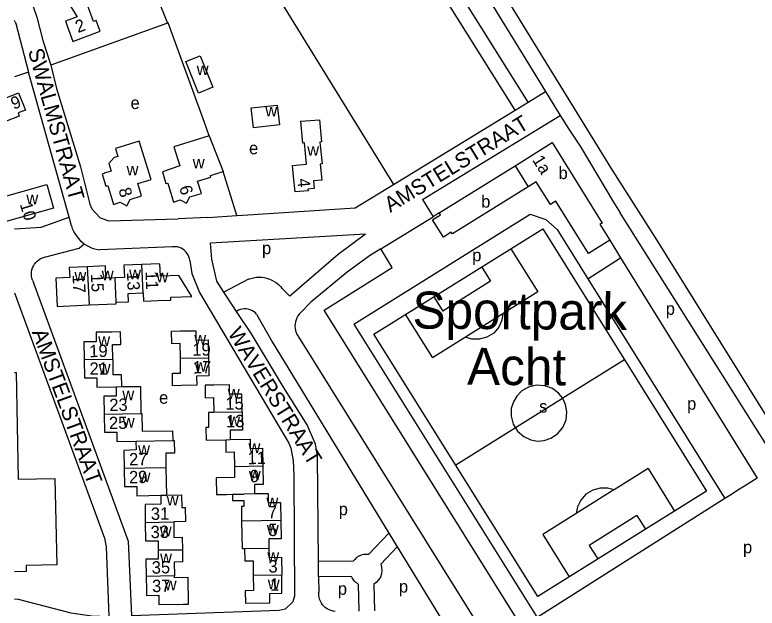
# Model space of a CAD drawing. Extents: x 156721 to 158827, y 386657 to 388950.
# Drawn here: x 158050.1 to 158290.7, y 387994 to 388186.3 of the extents above; entities that cross this region are included whole.
import ezdxf

# ---------------------------------------------------------------- set-up
doc = ezdxf.new("R2010")
doc.units = 0
for name, color, linetype in [('BLT_Basislijn', 7, 'Continuous'), ('BLT_Bebouwing', 7, 'Continuous'), ('BLT_Centroide', 7, 'Continuous'), ('BLT_Huisnummer', 7, 'Continuous'), ('BLT_Huisnummer_ tussenligend', 7, 'Continuous'), ('BLT_Onderverdeling_panden', 7, 'Continuous'), ('BLT_Sport_parknaam', 7, 'Continuous'), ('BLT_Straatnaam', 7, 'Continuous')]:
    doc.layers.add(name, color=color, linetype=linetype)

msp = doc.modelspace()

# ---------------------------------------------------------------- linework, layer by layer
at = {"layer": 'BLT_Basislijn'}
for p, q in [((158216.53, 388157.97), (158147.78, 388267.77)), ((158212.27, 388155.37), (158143.53, 388265.14)), ((158105, 388241.26), (158172.89, 388131.34)), ((158087.82, 388213.04), (158099.56, 388183.62)), ((158050.2, 388183.97), (158050, 388184.5)), ((158099.76, 388183.7), (158099.56, 388183.62)), ((158111.56, 388151.36), (158099.76, 388183.7)), ((158099.56, 388183.62), (158061.73, 388169.97)), ((158054.58, 388167.7), (158050, 388166.22)), ((158067.66, 388120.71), (158054.58, 388167.7)), ((158216.53, 388157.97), (158222.16, 388161.41)), ((158222.16, 388161.41), (158226.92, 388153.69)), ((158212.27, 388155.37), (158216.53, 388157.97)), ((158172.89, 388131.34), (158212.27, 388155.37)), ((158182.27, 388126.44), (158226.92, 388153.69)), ((158113.09, 388147.11), (158111.56, 388151.36)), ((158122.11, 388121.26), (158117.59, 388135.49)), ((158160.45, 388123.74), (158172.89, 388131.34)), ((158182.27, 388126.44), (158185.68, 388120.85)), ((158112.68, 388120.58), (158122.11, 388121.26)), ((158160.03, 388086), (158217.12, 388121.66)), ((158187.7, 388122.09), (158185.68, 388120.85)), ((158217.12, 388121.66), (158222.21, 388119.95)), ((158297.68, 388040.58), (158246.38, 388122.14)), ((158058.68, 388117.43), (158067.66, 388120.71)), ((158068.43, 388117.96), (158067.66, 388120.71)), ((158112.68, 388120.58), (158103.1, 388120.13)), ((158168.71, 388110.47), (158185.68, 388120.85)), ((158222.21, 388119.95), (158225.87, 388116.67)), ((158050, 388116.95), (158058.68, 388117.43)), ((158225.87, 388116.67), (158235.81, 388100.75)), ((158163.81, 388115.18), (158113.51, 388112.31)), ((158163.81, 388115.18), (158154.91, 388108.58)), ((158242.94, 388113.3), (158246.4, 388107.49)), ((158101.21, 388111.11), (158077.65, 388110.14)), ((158168.71, 388110.47), (158165.02, 388108.21)), ((158172.47, 388104.45), (158168.71, 388110.47)), ((158210.87, 388110.44), (158219.59, 388096.47)), ((158154.91, 388108.58), (158139.24, 388095.09)), ((158235.81, 388100.75), (158246.4, 388107.49)), ((158246.4, 388107.49), (158290.74, 388036.17)), ((158150.33, 388090.62), (158172.47, 388104.45)), ((158201.46, 388104.56), (158204.35, 388099.93)), ((158125.82, 388100.6), (158117.9, 388096.39)), ((158204.35, 388099.93), (158188.87, 388090.27)), ((158235.81, 388100.75), (158280.3, 388029.55)), ((158136.93, 388097.4), (158139.24, 388095.09)), ((158120.94, 388091.61), (158117.9, 388096.39)), ((158185.98, 388094.89), (158188.87, 388090.27)), ((158219.59, 388096.47), (158208.4, 388089.48)), ((158121.91, 388090.17), (158120.94, 388091.61)), ((158126.82, 388082.87), (158121.91, 388090.17)), ((158214.51, 387987.88), (158150.33, 388090.62)), ((158128.4, 388089.32), (158133.48, 388080.33)), ((158176.72, 388089.1), (158185.45, 388075.14)), ((158208.31, 388089.42), (158185.45, 388075.14)), ((158160.03, 388086), (158219.41, 387990.94)), ((158133.48, 388080.33), (158171.34, 388018.28)), ((158142.05, 388081.92), (158199.09, 387990.42)), ((158247.73, 388074.5), (158227.74, 388062.01)), ((158227.68, 388061.98), (158193.06, 388040.35)), ((158255.36, 388039.23), (158244.42, 388032.39)), ((158255.36, 388039.23), (158263.94, 388025.49)), ((158290.74, 388036.17), (158286.63, 388033.57)), ((158244.33, 388032.34), (158221.21, 388017.89)), ((158284.52, 388032.23), (158282.41, 388030.89)), ((158286.63, 388033.57), (158284.52, 388032.23)), ((158282.41, 388030.89), (158280.3, 388029.55)), ((158280.3, 388029.55), (158219.41, 387990.94)), ((158251.76, 388024.04), (158236.29, 388014.37)), ((158251.76, 388024.04), (158254.53, 388019.61)), ((158171.34, 388018.28), (158164.77, 388011.36)), ((158171.34, 388018.28), (158174.04, 388013.86)), ((158221.21, 388017.89), (158229.79, 388004.16)), ((158174.04, 388013.86), (158168.72, 388008.26)), ((158174.04, 388013.86), (158192.54, 387983.8)), ((158236.29, 388014.37), (158239.05, 388009.95)), ((158159.77, 388009.22), (158148.53, 388009.14)), ((158148.57, 388004.14), (158148.53, 388009.14)), ((158159.29, 388004.22), (158148.57, 388004.14)), ((158148.57, 388004.14), (158148.61, 387999.21)), ((158161.45, 388001.83), (158161.64, 387993.07)), ((158166.45, 388001.8), (158166.64, 387993.15))]:
    msp.add_line(p, q, dxfattribs=at)
for points in [[(158087.6, 388388.98), (158120.58, 388335.72), (158121.32, 388334.13), (158168.5, 388258.11), (158180.9, 388237.55), (158193.49, 388217.63), (158243.23, 388136.8), (158258.3, 388113.07), (158338.44, 387984.38), (158433.27, 387830.65)], [(158157.81, 388264.96), (158189.98, 388213.68), (158222.16, 388161.41)], [(158054.85, 388192.54), (158057.24, 388185.58), (158059.18, 388178.02), (158061.73, 388169.97)], [(158050.2, 388183.97), (158050.41, 388183.44), (158054.58, 388167.7)], [(158061.73, 388169.97), (158063.64, 388162.44), (158071.36, 388137.04), (158074.42, 388124.88), (158075.04, 388123.39), (158077.78, 388120.52), (158080.62, 388119.56), (158103.1, 388120.13)], [(158226.92, 388153.69), (158229.68, 388149.2), (158233.35, 388143.7), (158244.21, 388125.6), (158246.38, 388122.14)], [(158122.11, 388121.26), (158124.02, 388121.4), (158160.45, 388123.74)], [(158068.43, 388117.96), (158068.72, 388117.08), (158069.09, 388116.22), (158069.53, 388115.4), (158070.05, 388114.62), (158070.62, 388113.88), (158071.26, 388113.2), (158071.95, 388112.57), (158072.56, 388112.11)], [(158060.15, 388107.89), (158071, 388110.63), (158072.56, 388112.11)], [(158072.56, 388112.11), (158072.69, 388112.01), (158073.48, 388111.51), (158074.31, 388111.08), (158075.18, 388110.72), (158076.07, 388110.44), (158076.98, 388110.24), (158077.65, 388110.14)], [(158117.9, 388096.39), (158115.61, 388099.99), (158114, 388107.09), (158113.51, 388112.31)], [(158106.79, 388106.65), (158106.69, 388107.27), (158106.52, 388107.88), (158106.27, 388108.45), (158105.95, 388108.99), (158105.56, 388109.49), (158105.11, 388109.93), (158104.61, 388110.32), (158104.07, 388110.63), (158103.49, 388110.88), (158102.88, 388111.05), (158102.26, 388111.14), (158101.63, 388111.15), (158101.21, 388111.11)], [(158055.84, 388100.29), (158055.64, 388100.93), (158055.52, 388101.6), (158055.48, 388102.27), (158055.52, 388102.95), (158055.64, 388103.61), (158055.84, 388104.26), (158056.11, 388104.88), (158056.46, 388105.46), (158056.87, 388106), (158057.34, 388106.48), (158057.86, 388106.91), (158058.43, 388107.27), (158059.04, 388107.56), (158059.68, 388107.78), (158060.15, 388107.89)], [(158165.02, 388108.21), (158157.8, 388102.89), (158146.07, 388093.13), (158142.74, 388089.76)], [(158106.79, 388106.65), (158107.45, 388102.46), (158110.01, 388096.33), (158138.9, 388047.47), (158139.54, 388045.87), (158140.34, 388041.81), (158140.5, 388037.02), (158140.79, 387997.94), (158140.18, 387996.05), (158137.77, 387993.71), (158135.81, 387993.26), (158087.96, 387991.51)], [(158055.84, 388100.29), (158086.82, 388015.72), (158087.96, 387991.51)], [(158125.82, 388100.6), (158126.64, 388100.88), (158127.48, 388101.09), (158128.34, 388101.22), (158129.21, 388101.27), (158130.08, 388101.24), (158130.94, 388101.13), (158131.79, 388100.94), (158132.62, 388100.67), (158133.42, 388100.33), (158134.18, 388099.92), (158134.9, 388099.44), (158135.58, 388098.89), (158136.2, 388098.28), (158136.77, 388097.62), (158136.93, 388097.4)], [(158050, 388096.15), (158079.12, 388016.74), (158079.71, 388013.9), (158080.59, 387991.28)], [(158128.4, 388089.32), (158127.96, 388089.77), (158127.46, 388090.15), (158126.91, 388090.47), (158126.33, 388090.72), (158125.73, 388090.89), (158125.1, 388090.99), (158124.47, 388091), (158123.84, 388090.93), (158123.23, 388090.79), (158122.64, 388090.57), (158122.08, 388090.28), (158121.91, 388090.17)], [(158142.74, 388089.76), (158142.27, 388089.25), (158141.86, 388088.69), (158141.52, 388088.09), (158141.25, 388087.45), (158141.06, 388086.79), (158140.94, 388086.1), (158140.9, 388085.41), (158140.95, 388084.72), (158141.07, 388084.04), (158141.27, 388083.37), (158141.55, 388082.74), (158141.9, 388082.14), (158142.05, 388081.92)], [(158208.34, 388089.44), (158208, 388087.29), (158207.02, 388085.11), (158205.35, 388083.16), (158203.13, 388081.78), (158200.65, 388081.13), (158198.25, 388081.2), (158196.18, 388081.84)], [(158148.53, 388009.14), (158148.24, 388043.32), (158147.53, 388047.15), (158144.91, 388053.47), (158137.23, 388065.6), (158126.82, 388082.87)], [(158227.7, 388062.01), (158226.34, 388063.7), (158224.4, 388065.15), (158221.96, 388066.08), (158219.26, 388066.27), (158216.64, 388065.66), (158214.43, 388064.39), (158212.78, 388062.73), (158211.7, 388060.91), (158211.05, 388058.74), (158210.98, 388056.25), (158211.65, 388053.68), (158213.07, 388051.37), (158215.06, 388049.62), (158217.32, 388048.57), (158219.55, 388048.18), (158221.66, 388048.32), (158223.88, 388049.05), (158226.01, 388050.46), (158227.73, 388052.52), (158228.78, 388055.02), (158229.05, 388057.61), (158228.62, 388060), (158227.72, 388061.97)], [(158244.37, 388032.36), (158242.27, 388032.93), (158239.88, 388032.95), (158237.44, 388032.27), (158235.24, 388030.9), (158233.56, 388029), (158232.53, 388026.85), (158232.12, 388024.71)], [(158164.77, 388011.36), (158163.98, 388011.42), (158163.17, 388011.36), (158162.35, 388011.16), (158161.58, 388010.83), (158160.88, 388010.38), (158160.27, 388009.83), (158159.77, 388009.22)], [(158168.72, 388008.26), (158169.01, 388007.29), (158169.11, 388006.23), (158168.97, 388005.13), (158168.6, 388004.08), (158168.02, 388003.14), (158167.28, 388002.37), (158166.45, 388001.8)], [(158161.45, 388001.83), (158161.06, 388002.08), (158160.69, 388002.36), (158160.34, 388002.68), (158160.02, 388003.03), (158159.74, 388003.4), (158159.5, 388003.8), (158159.29, 388004.22)], [(158153.97, 387992.94), (158153.3, 387993.03), (158152.63, 387993.21), (158152, 387993.45), (158151.39, 387993.77), (158150.83, 387994.16), (158150.32, 387994.62), (158149.87, 387995.12), (158149.47, 387995.68), (158149.15, 387996.28), (158148.89, 387996.92), (158148.72, 387997.58), (158148.62, 387998.25), (158148.6, 387998.94), (158148.61, 387999.21)], [(158050, 387997.06), (158051.18, 387996.93), (158068.22, 387992.53), (158075.01, 387991.54), (158080.59, 387991.28)]]:
    msp.add_lwpolyline(points, dxfattribs=at)
for points in [[(158105.53, 388171.11), (158110.13, 388172.98), (158114.28, 388162.81), (158109.67, 388160.93)], [(158219.62, 387997.74), (158166.49, 388082.77), (158221.25, 388116.98), (158274.37, 388031.95)]]:
    msp.add_lwpolyline(points, close=True, dxfattribs=at)
at = {"layer": 'BLT_Bebouwing'}
for p, q in [((158113.09, 388147.11), (158117.59, 388135.49)), ((158099.09, 388039.52), (158099.23, 388030.61))]:
    msp.add_line(p, q, dxfattribs=at)
for points in [[(158079.25, 388201.85), (158065.52, 388193.28), (158070.3, 388185.69), (158066.47, 388184.26), (158068.94, 388177.67), (158077.79, 388180.97), (158076.49, 388184.46), (158075.6, 388184.12), (158073.59, 388189.77), (158083.1, 388195.68)], [(158044.71, 388162.69), (158046.2, 388158.97), (158051.31, 388161.01), (158053.51, 388155.44), (158051.13, 388154.52), (158051.55, 388153.5), (158047.11, 388151.74), (158046.7, 388152.76), (158042.39, 388151.04), (158040.41, 388155.99), (158038.55, 388155.25), (158036.82, 388159.57)], [(158044.37, 388126.76), (158060.46, 388131.33), (158062.67, 388123.65), (158046.55, 388119.07)]]:
    msp.add_lwpolyline(points, close=True, dxfattribs=at)
for points in [[(158126.71, 388156.1), (158135.15, 388157.06), (158135.89, 388150.6), (158127.45, 388149.64), (158126.71, 388156.1)], [(158143.99, 388144.76), (158143.47, 388144.71), (158142.77, 388151.81), (158148.81, 388152.21), (158149.52, 388145.1), (158148.99, 388145.05)], [(158089.92, 388131.62), (158094.24, 388132.95), (158090.42, 388145.3), (158082.77, 388142.93), (158083.5, 388140.41), (158082.31, 388140.07), (158080.61, 388138.07), (158081.33, 388135.59), (158079.02, 388134.93), (158079.06, 388134.82), (158078.41, 388134.62), (158079.59, 388130.79), (158080.2, 388130.98), (158082.09, 388124.86), (158084.29, 388125.54), (158086.36, 388124.44), (158087.44, 388126.49), (158091.15, 388127.64), (158089.92, 388131.62)], [(158113.09, 388147.11), (158101.65, 388143.55), (158103.59, 388137.3), (158097.93, 388135.45), (158099.1, 388131.61), (158099.65, 388131.78), (158101.5, 388125.63), (158103.7, 388126.32), (158105.77, 388125.22), (158106.88, 388127.26), (158110.59, 388128.41), (158109.36, 388132.41), (158113.62, 388133.73), (158113.48, 388134.21), (158117.59, 388135.49)], [(158148.99, 388145.05), (158149.7, 388137.98), (158149.07, 388137.92), (158149.59, 388132.76), (158146.9, 388132.49), (158147.15, 388129.98), (158145.1, 388129.77), (158145.14, 388129.3), (158140.93, 388128.88), (158140.43, 388133.85), (158140.07, 388137.46), (158144.67, 388137.92), (158143.99, 388144.76)], [(158212.26, 388137.37), (158224.3, 388144.86), (158240.45, 388118.82), (158239.77, 388118.4), (158242.94, 388113.3)], [(158187.7, 388122.09), (158212.26, 388137.37)], [(158242.94, 388113.3), (158236.05, 388108.94), (158225.5, 388125.94), (158223.71, 388124.84), (158219.14, 388132.19), (158216.54, 388130.58)], [(158216.54, 388130.58), (158191.93, 388115.31), (158191.58, 388115.87), (158189.02, 388114.27), (158185.53, 388119.86), (158188.09, 388121.46), (158187.7, 388122.09)], [(158073.6, 388104.67), (158067.73, 388104.43), (158067.88, 388101.2), (158063.44, 388101), (158063.86, 388091.81), (158074.15, 388092.27)], [(158082.63, 388101.02), (158079.61, 388100.9), (158079.46, 388104.91), (158073.6, 388104.67)], [(158091.3, 388105.38), (158085.45, 388105.14), (158085.61, 388101.13), (158082.63, 388101.02)], [(158091.67, 388096.21), (158091.77, 388093.51), (158096.59, 388093.7), (158100.66, 388093.86), (158100.62, 388094.76), (158107.52, 388095.03), (158103.25, 388101.86), (158097.31, 388101.63), (158097.15, 388105.61), (158091.3, 388105.38)], [(158082.93, 388093.17), (158086.95, 388093.32), (158086.85, 388096.02), (158091.67, 388096.21)], [(158074.15, 388092.27), (158082.95, 388092.67), (158082.93, 388093.17)], [(158081.83, 388074.58), (158081.75, 388079.42), (158084.42, 388079.46), (158084.36, 388083.54), (158081.43, 388083.5), (158076.43, 388083.42), (158076.48, 388080.36), (158072.48, 388080.3), (158072.58, 388074.44)], [(158103.75, 388074.98), (158103.66, 388079.77), (158100.98, 388079.72), (158100.9, 388083.77), (158103.77, 388083.83), (158108.77, 388083.92), (158108.82, 388080.87), (158112.82, 388080.93), (158112.91, 388075.15)], [(158072.58, 388074.44), (158072.68, 388068.6), (158076.67, 388068.67), (158076.72, 388065.63), (158082.93, 388065.73)], [(158081.83, 388074.58), (158081.9, 388069.74), (158084.59, 388069.78), (158084.65, 388065.8)], [(158112.91, 388075.15), (158113.01, 388069.26), (158109.04, 388069.18), (158109.09, 388066.24), (158104.09, 388066.14), (158101.25, 388066.09), (158101.18, 388070.14), (158103.84, 388070.19), (158103.75, 388074.98)], [(158050, 388070.38), (158050.49, 388070.39), (158051.23, 388035.79), (158063.11, 388036.04), (158063.7, 388008.04), (158053.72, 388007.83), (158053.76, 388005.84), (158050, 388005.76)], [(158084.65, 388065.8), (158090.85, 388065.89), (158090.98, 388057.04)], [(158123.8, 388057.57), (158123.71, 388063.41), (158119.71, 388063.35), (158119.66, 388066.4), (158114.66, 388066.32), (158111.78, 388066.28), (158111.85, 388062.2), (158114.52, 388062.24), (158114.6, 388057.42)], [(158082.93, 388065.73), (158082.98, 388062.76), (158078.96, 388062.7), (158079.06, 388056.85)], [(158079.06, 388056.85), (158079.16, 388051), (158083.16, 388051.04), (158083.18, 388048), (158089.31, 388048.18)], [(158090.98, 388057.04), (158091.31, 388057.05), (158091.39, 388051.38), (158101.26, 388051.52), (158101.3, 388048.29)], [(158114.6, 388057.42), (158112.84, 388057.39), (158112.92, 388052.57), (158112, 388052.56), (158112.07, 388048.48), (158118.47, 388048.58)], [(158123.8, 388057.57), (158123.89, 388051.72), (158119.89, 388051.65), (158119.95, 388048.69)], [(158089.31, 388048.18), (158089.4, 388045.27), (158085.43, 388045.15), (158085.53, 388039.29)], [(158101.3, 388048.29), (158101.75, 388048.29), (158101.82, 388044.25), (158099.01, 388044.21), (158099.09, 388039.52)], [(158118.47, 388048.58), (158118.54, 388044.61), (158121.21, 388044.65), (158121.29, 388039.82)], [(158119.95, 388048.69), (158126.37, 388048.81), (158126.42, 388045.77), (158130.41, 388045.83), (158130.51, 388039.98)], [(158085.53, 388039.29), (158085.63, 388033.42), (158089.61, 388033.48), (158089.66, 388030.43), (158097.41, 388030.6)], [(158121.29, 388039.82), (158121.34, 388036.33), (158115.33, 388036.23), (158115.42, 388030.82), (158118.75, 388030.88), (158120.62, 388030.91)], [(158130.51, 388039.98), (158130.61, 388034.12), (158127.76, 388034.08), (158127.8, 388031.15)], [(158097.41, 388030.6), (158097.47, 388027.67), (158092.31, 388027.55), (158092.4, 388021.69)], [(158099.23, 388030.61), (158104.13, 388030.69), (158104.19, 388026.62), (158105.32, 388026.64), (158105.39, 388022.07), (158101.59, 388022.01), (158101.59, 388021.84)], [(158120.62, 388030.91), (158120.65, 388028.89), (158124.33, 388028.95), (158124.36, 388026.99), (158123.55, 388026.98), (158123.62, 388022.18)], [(158127.8, 388031.15), (158132.21, 388031.22), (158132.25, 388028.2), (158136.23, 388028.26), (158136.33, 388022.4)], [(158092.4, 388021.69), (158092.5, 388015.84), (158096.51, 388015.87), (158096.54, 388012.88)], [(158101.59, 388021.84), (158101.67, 388016.95), (158104.34, 388017), (158104.41, 388012.95)], [(158123.62, 388022.18), (158123.76, 388013.33), (158124.6, 388013.34)], [(158136.33, 388022.4), (158136.43, 388016.53), (158132.43, 388016.47), (158132.48, 388013.47)], [(158096.54, 388012.88), (158096.57, 388009.88), (158092.58, 388009.84), (158092.67, 388004.32)], [(158104.41, 388012.95), (158104.47, 388008.98), (158101.78, 388008.93), (158101.85, 388004.47)], [(158124.6, 388013.34), (158124.66, 388009.32), (158127.33, 388009.36), (158127.41, 388004.68)], [(158132.48, 388013.47), (158132.53, 388010.46), (158136.53, 388010.53), (158136.61, 388004.83)], [(158092.67, 388004.32), (158092.75, 388000), (158092.78, 387998.14), (158096.77, 387998.2), (158096.8, 387995.15), (158104.68, 387995.29), (158106.43, 387995.32), (158106.27, 388003.92), (158101.86, 388003.84), (158101.85, 388004.47)], [(158127.41, 388004.68), (158127.49, 388000), (158127.49, 387999.71), (158124.81, 387999.67), (158124.88, 387995.59), (158132.74, 387995.72), (158132.72, 387998.76), (158136.7, 387998.83), (158136.68, 388000), (158136.61, 388004.83)]]:
    msp.add_lwpolyline(points, dxfattribs=at)
at = {"layer": 'BLT_Onderverdeling_panden'}
for p, q in [((158212.26, 388137.37), (158216.54, 388130.58)), ((158073.6, 388104.67), (158074.15, 388092.27)), ((158091.67, 388096.21), (158091.3, 388105.38)), ((158082.93, 388093.17), (158082.63, 388101.02)), ((158081.83, 388074.58), (158072.58, 388074.44)), ((158103.75, 388074.98), (158112.91, 388075.15)), ((158082.93, 388065.73), (158084.65, 388065.8)), ((158079.06, 388056.85), (158090.98, 388057.04)), ((158123.8, 388057.57), (158114.6, 388057.42)), ((158089.31, 388048.18), (158101.3, 388048.29)), ((158118.47, 388048.58), (158119.95, 388048.69)), ((158099.09, 388039.52), (158085.53, 388039.29)), ((158130.51, 388039.98), (158121.29, 388039.82)), ((158097.41, 388030.6), (158099.23, 388030.61)), ((158101.59, 388021.84), (158092.4, 388021.69)), ((158136.33, 388022.4), (158123.62, 388022.18)), ((158096.54, 388012.88), (158104.41, 388012.95)), ((158124.6, 388013.34), (158132.48, 388013.47)), ((158101.85, 388004.47), (158092.67, 388004.32)), ((158127.41, 388004.68), (158136.61, 388004.83))]:
    msp.add_line(p, q, dxfattribs=at)
msp.add_lwpolyline([(158120.62, 388030.91), (158124.29, 388030.97), (158124.29, 388031.09), (158127.8, 388031.15)], dxfattribs=at)

# ---------------------------------------------------------------- texts
at = {"layer": 'BLT_Centroide'}
for s, p in [('w', (158109.05, 388166.75)), ('e', (158087.61, 388155.77)), ('w', (158131.3, 388153.34)), ('e', (158126.03, 388141.1)), ('w', (158144.88, 388140.62)), ('w', (158107.77, 388136.5)), ('w', (158086.33, 388134.25)), ('b', (158226.36, 388133.05)), ('w', (158053.84, 388124.91)), ('b', (158201.27, 388123.81)), ('p', (158130.24, 388108.71)), ('p', (158198.37, 388106.43)), ('w', (158069.42, 388099.92)), ('w', (158078.27, 388100.28)), ('w', (158087.14, 388100.62)), ('w', (158095.98, 388099.62)), ('p', (158261.11, 388089.09)), ('w', (158077.12, 388079)), ('w', (158108.26, 388079.44)), ('w', (158077.27, 388070.09)), ('w', (158108.41, 388070.62)), ('w', (158084.95, 388061.38)), ('e', (158096.86, 388060.26)), ('w', (158119.13, 388061.91)), ('p', (158268.02, 388058.32)), ('s', (158220.07, 388057.38)), ('w', (158085.07, 388052.53)), ('w', (158119.27, 388053.03)), ('w', (158090.05, 388043.69)), ('w', (158125.83, 388044.31)), ('w', (158090.2, 388034.88)), ('w', (158125.98, 388035.44)), ('w', (158099.31, 388027.28)), ('w', (158131.65, 388026.72)), ('p', (158155.1, 388024.12)), ('w', (158097.07, 388017.31)), ('w', (158131.8, 388017.88)), ('p', (158286.16, 388011.8)), ('w', (158097.19, 388008.62)), ('w', (158131.94, 388009.06)), ('w', (158132.09, 388000.22)), ('w', (158098.67, 387999.8)), ('p', (158154.81, 387998.35)), ('p', (158174.61, 387999.06))]:
    msp.add_text(s, height=4, dxfattribs=at).set_placement(p)
at = {"layer": 'BLT_Huisnummer'}
for s, rotation, p in [('2', 20.5674, (158070.57, 388180.36)), ('9', 21.7626, (158049.75, 388155.5)), ('1a', 302.2173, (158217.7, 388139.25)), ('4', 275.7266, (158141.68, 388133.14)), ('6', 286.7557, (158103.34, 388130.38)), ('8', 287.1725, (158083.63, 388129.62)), ('10', 286.4867, (158051.68, 388124.95)), ('11', 272.3021, (158092.45, 388103.09)), ('17', 272.3314, (158068.81, 388102.02)), ('19', 1.0051, (158074.27, 388075.32)), ('19', 0.9476, (158107.67, 388075.77)), ('17', 0.9476, (158107.87, 388070.04)), ('23', 1.0051, (158080.76, 388057.86)), ('15', 0.9476, (158118.37, 388058.31)), ('27', 1.0051, (158087.17, 388040.27)), ('11', 0.9476, (158125.56, 388040.64)), ('31', 1.0051, (158094.23, 388022.59)), ('7', 0.9476, (158132.17, 388023.14)), ('37', 1.0051, (158094.62, 387999.2)), ('1', 0.9476, (158132.85, 387999.69))]:
    msp.add_text(s, height=4, rotation=rotation, dxfattribs=at).set_placement(p)
at = {"layer": 'BLT_Huisnummer_ tussenligend'}
for s, rotation, p in [('15', 272.3443, (158074.75, 388102.32)), ('13', 272.2849, (158086.43, 388102.86)), ('21', 1.0051, (158074.36, 388069.62)), ('13', 0.9476, (158118.59, 388052.58)), ('25', 1.0051, (158080.65, 388052.02)), ('29', 1.0051, (158087.15, 388034.46)), ('9', 0.9476, (158126.35, 388034.81)), ('33', 1.0051, (158094.16, 388016.69)), ('5', 0.9476, (158132.29, 388017.35)), ('35', 1.0051, (158094.51, 388005.2)), ('3', 0.9476, (158132.35, 388005.52))]:
    msp.add_text(s, height=4, rotation=rotation, dxfattribs=at).set_placement(p)
at = {"layer": 'BLT_Sport_parknaam'}
for s, p in [('Sportpark', (158178.98, 388084.63)), ('Acht', (158196.68, 388066.41))]:
    msp.add_text(s, height=12, rotation=359.5956, dxfattribs=at).set_placement(p)
at = {"layer": 'BLT_Straatnaam'}
for s, rotation, p in [('SWALMSTRAAT', 285.5573, (158054.31, 388174.68)), ('AMSTELSTRAAT', 31.4198, (158171.81, 388122.08)), ('WAVERSTRAAT', 301.6517, (158118.96, 388083.13)), ('AMSTELSTRAAT', 290.149, (158055.58, 388083.49))]:
    msp.add_text(s, height=5, rotation=rotation, dxfattribs=at).set_placement(p)

doc.saveas('drawing.dxf')
